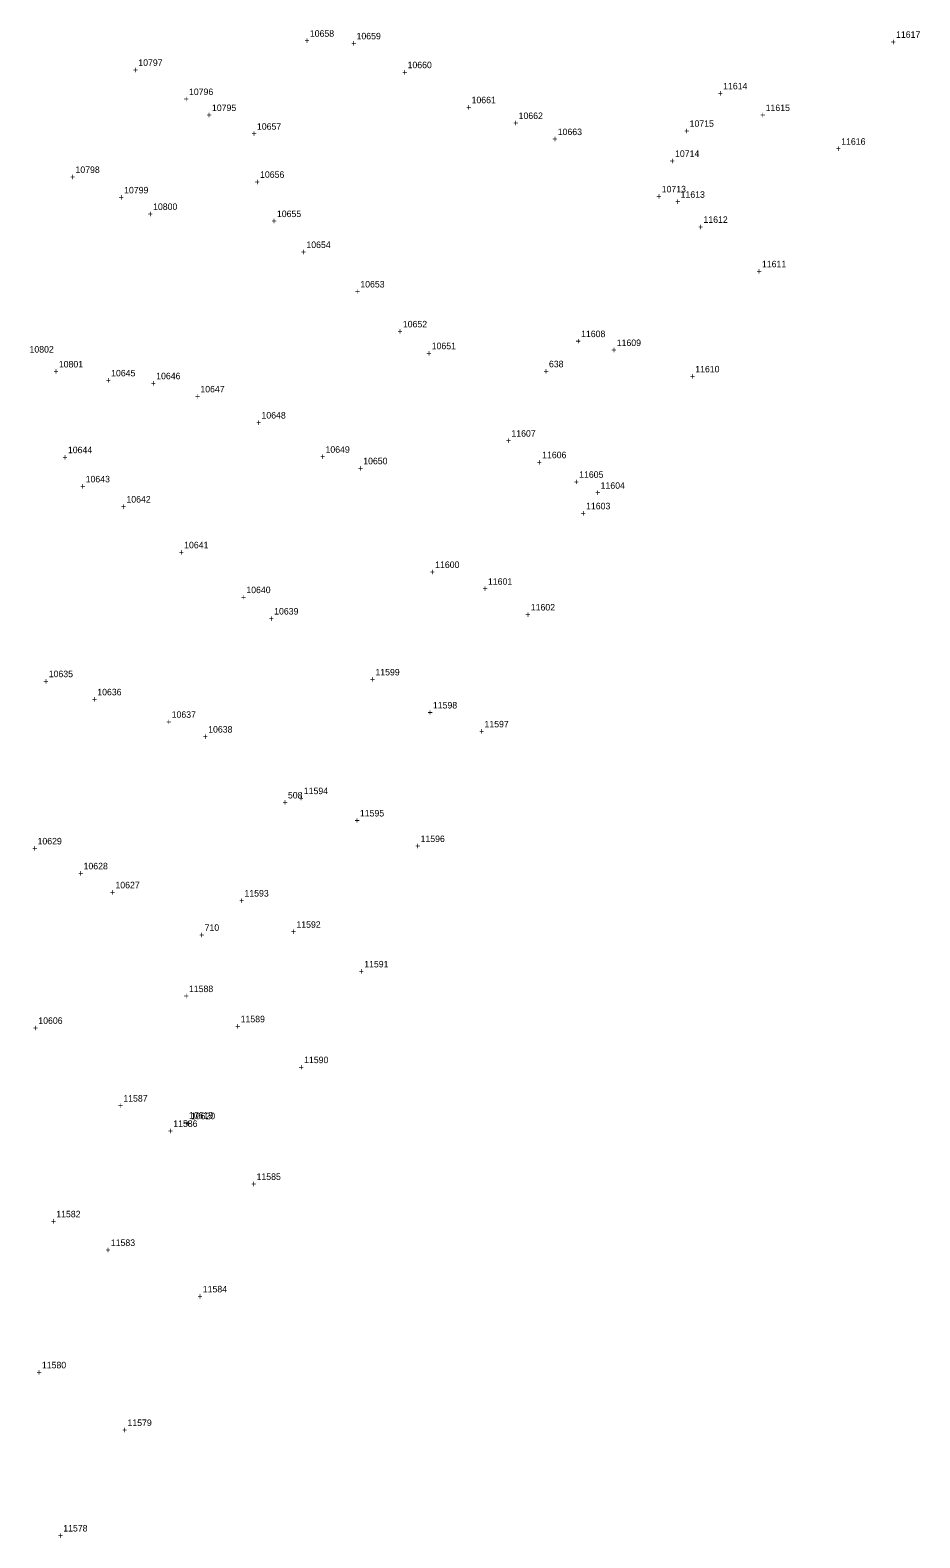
# Model space of a CAD drawing. Extents: x 1160051 to 1162814, y 614604 to 619560.
# Drawn here: x 1162159 to 1162500, y 618363 to 618941 of the extents above; entities that cross this region are included whole.
import ezdxf

# ---------------------------------------------------------------- set-up
doc = ezdxf.new("R2010")
doc.units = 0
for name, color, linetype in [('S_Control_Temp_Traverse', 7, 'Continuous'), ('S_Control_Traverse_Point', 7, 'Continuous'), ('S_Drainage_Culvert_Top', 7, 'Continuous'), ('S_Drainage_Invert', 7, 'Continuous'), ('S_Ground_Elevation', 7, 'Continuous'), ('S_Guardrail_Beam', 7, 'Continuous'), ('S_Traffic_Sign_DoublePost', 7, 'Continuous'), ('S_Trees_TreeLine', 7, 'Continuous')]:
    doc.layers.add(name, color=color, linetype=linetype)

msp = doc.modelspace()

# ---------------------------------------------------------------- texts
at = {"layer": 'S_Control_Temp_Traverse'}
for s, p in [('638', (1162358.17, 618811.59)), ('+', (1162356.11, 618808.84))]:
    msp.add_text(s, height=2.5, dxfattribs=at).set_placement(p)
at = {"layer": 'S_Control_Traverse_Point'}
for s, p in [('508', (1162258.13, 618646.26)), ('508', (1162258.13, 618646.26)), ('508', (1162258.13, 618646.26)), ('508', (1162258.13, 618646.26)), ('+', (1162256.07, 618643.51)), ('+', (1162256.07, 618643.51)), ('+', (1162256.07, 618643.51)), ('+', (1162256.07, 618643.51)), ('+', (1162224.16, 618592.73)), ('+', (1162224.16, 618592.73)), ('+', (1162224.16, 618592.73)), ('710', (1162226.22, 618595.48)), ('710', (1162226.22, 618595.48)), ('710', (1162226.22, 618595.48))]:
    msp.add_text(s, height=2.5, dxfattribs=at).set_placement(p)
at = {"layer": 'S_Drainage_Culvert_Top'}
for s, p in [('10619', (1162220.22, 618523.53)), ('+', (1162218.16, 618520.78))]:
    msp.add_text(s, height=2.5, dxfattribs=at).set_placement(p)
at = {"layer": 'S_Drainage_Invert'}
for s, p in [('10620', (1162220.95, 618523.27)), ('+', (1162218.89, 618520.52))]:
    msp.add_text(s, height=2.5, dxfattribs=at).set_placement(p)
at = {"layer": 'S_Ground_Elevation'}
for s, p in [('+', (1162264.48, 618935.56)), ('10658', (1162266.54, 618938.31)), ('+', (1162282.38, 618934.57)), ('10659', (1162284.44, 618937.32)), ('+', (1162489.11, 618935.15)), ('11617', (1162491.17, 618937.9)), ('10797', (1162200.8, 618927.14)), ('+', (1162198.74, 618924.39)), ('+', (1162301.92, 618923.51)), ('10660', (1162303.99, 618926.26)), ('10796', (1162220.22, 618915.96)), ('11614', (1162424.92, 618918.15)), ('+', (1162218.16, 618913.21)), ('10795', (1162229.03, 618909.83)), ('10661', (1162328.52, 618912.83)), ('+', (1162422.86, 618915.4)), ('11615', (1162441.21, 618909.83)), ('+', (1162226.97, 618907.08)), ('+', (1162326.46, 618910.08)), ('10662', (1162346.55, 618906.77)), ('+', (1162439.15, 618907.08)), ('+', (1162244.21, 618899.92)), ('10657', (1162246.27, 618902.67)), ('+', (1162344.49, 618904.02)), ('10663', (1162361.54, 618900.61)), ('+', (1162359.47, 618897.86)), ('+', (1162468.1, 618894.15)), ('11616', (1162470.16, 618896.9)), ('+', (1162174.67, 618883.34)), ('10798', (1162176.73, 618886.09)), ('+', (1162245.39, 618881.47)), ('10656', (1162247.46, 618884.22)), ('10799', (1162195.36, 618878.26)), ('11613', (1162408.63, 618876.57)), ('+', (1162193.3, 618875.51)), ('10800', (1162206.47, 618871.91)), ('+', (1162406.56, 618873.82)), ('+', (1162204.41, 618869.16)), ('+', (1162415.32, 618864.22)), ('11612', (1162417.38, 618866.97)), ('+', (1162263.16, 618854.57)), ('10654', (1162265.22, 618857.32)), ('+', (1162437.73, 618847.17)), ('11611', (1162439.79, 618849.92)), ('10653', (1162285.88, 618842.18)), ('+', (1162283.82, 618839.43)), ('+', (1162300.12, 618824.13)), ('10652', (1162302.18, 618826.88)), ('11608', (1162370.49, 618823.14)), ('10651', (1162313.24, 618818.51)), ('+', (1162368.43, 618820.39)), ('11609', (1162384.15, 618819.73)), ('10802', (1162159.11, 618817.21)), ('10801', (1162170.35, 618811.52)), ('+', (1162311.18, 618815.76)), ('+', (1162382.09, 618816.98)), ('+', (1162168.29, 618808.77)), ('10645', (1162190.39, 618808.09)), ('10646', (1162207.66, 618806.99)), ('+', (1162412.18, 618806.87)), ('11610', (1162414.24, 618809.62)), ('+', (1162188.33, 618805.34)), ('+', (1162205.6, 618804.24)), ('10647', (1162224.58, 618801.95)), ('+', (1162222.51, 618799.2)), ('+', (1162245.95, 618789.18)), ('10648', (1162248.01, 618791.93)), ('11607', (1162343.79, 618784.97)), ('10644', (1162173.82, 618778.65)), ('10649', (1162272.54, 618778.81)), ('+', (1162341.73, 618782.22)), ('+', (1162171.75, 618775.9)), ('+', (1162270.48, 618776.06)), ('+', (1162284.94, 618771.65)), ('10650', (1162287, 618774.4)), ('+', (1162353.49, 618773.97)), ('11606', (1162355.56, 618776.72)), ('10643', (1162180.62, 618767.46)), ('+', (1162178.56, 618764.71)), ('10642', (1162196.25, 618759.71)), ('+', (1162194.19, 618756.96)), ('+', (1162370.33, 618754.38)), ('11603', (1162372.39, 618757.13)), ('10641', (1162218.37, 618742.18)), ('+', (1162216.31, 618739.43)), ('+', (1162312.5, 618731.88)), ('11600', (1162314.56, 618734.63)), ('10640', (1162242.2, 618724.98)), ('+', (1162332.73, 618725.44)), ('11601', (1162334.79, 618728.19)), ('+', (1162240.14, 618722.23)), ('+', (1162250.8, 618714.03)), ('10639', (1162252.86, 618716.78)), ('+', (1162349.14, 618715.58)), ('11602', (1162351.21, 618718.33)), ('10635', (1162166.48, 618692.76)), ('+', (1162289.61, 618690.68)), ('11599', (1162291.67, 618693.43)), ('+', (1162164.42, 618690.01)), ('10636', (1162185.08, 618685.8)), ('+', (1162183.02, 618683.05)), ('11598', (1162313.7, 618680.76)), ('+', (1162211.53, 618674.43)), ('10637', (1162213.59, 618677.18)), ('+', (1162311.63, 618678.01)), ('11597', (1162333.46, 618673.51)), ('+', (1162225.52, 618668.76)), ('10638', (1162227.58, 618671.51)), ('+', (1162331.4, 618670.76)), ('+', (1162262.17, 618645.16)), ('11594', (1162264.23, 618647.91)), ('11595', (1162285.72, 618639.35)), ('+', (1162283.66, 618636.6)), ('10629', (1162162.19, 618628.64)), ('11596', (1162308.97, 618629.54)), ('+', (1162160.13, 618625.89)), ('+', (1162306.91, 618626.79)), ('+', (1162177.77, 618616.33)), ('10628', (1162179.83, 618619.08)), ('10627', (1162192.04, 618611.81)), ('+', (1162189.98, 618609.06)), ('+', (1162239.42, 618605.89)), ('11593', (1162241.48, 618608.64)), ('+', (1162259.34, 618593.92)), ('11592', (1162261.4, 618596.67)), ('11591', (1162287.37, 618581.47)), ('+', (1162285.31, 618578.72)), ('+', (1162218.16, 618569.26)), ('11588', (1162220.22, 618572.01)), ('10606', (1162162.48, 618559.82)), ('+', (1162237.95, 618557.69)), ('11589', (1162240.02, 618560.44)), ('+', (1162160.42, 618557.07)), ('+', (1162262.28, 618542.02)), ('11590', (1162264.34, 618544.77)), ('11587', (1162195.07, 618530.02)), ('+', (1162193.01, 618527.27)), ('+', (1162212.14, 618517.57)), ('11586', (1162214.2, 618520.32)), ('11585', (1162246.12, 618500)), ('+', (1162244.06, 618497.25)), ('+', (1162167.3, 618482.9)), ('11582', (1162169.36, 618485.65)), ('+', (1162188.21, 618471.93)), ('11583', (1162190.27, 618474.68)), ('+', (1162223.46, 618454.13)), ('11584', (1162225.52, 618456.88)), ('+', (1162161.8, 618425.01)), ('11580', (1162163.86, 618427.76)), ('+', (1162194.6, 618402.89)), ('11579', (1162196.66, 618405.64)), ('+', (1162169.98, 618362.44)), ('11578', (1162172.04, 618365.19))]:
    msp.add_text(s, height=2.5, dxfattribs=at).set_placement(p)
at = {"layer": 'S_Guardrail_Beam'}
for s, p in [('+', (1162410.02, 618901.03)), ('10715', (1162412.08, 618903.78)), ('+', (1162404.43, 618889.49)), ('10714', (1162406.49, 618892.24)), ('+', (1162399.31, 618875.89)), ('10713', (1162401.37, 618878.64))]:
    msp.add_text(s, height=2.5, dxfattribs=at).set_placement(p)
at = {"layer": 'S_Traffic_Sign_DoublePost'}
for s, p in [('+', (1162367.68, 618766.45)), ('11605', (1162369.74, 618769.2)), ('+', (1162375.91, 618762.25)), ('11604', (1162377.97, 618765))]:
    msp.add_text(s, height=2.5, dxfattribs=at).set_placement(p)
at = {"layer": 'S_Trees_TreeLine'}
for s, p in [('+', (1162251.86, 618866.42)), ('10655', (1162253.92, 618869.17))]:
    msp.add_text(s, height=2.5, dxfattribs=at).set_placement(p)

doc.saveas('drawing.dxf')
